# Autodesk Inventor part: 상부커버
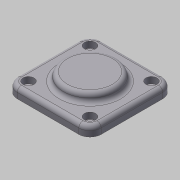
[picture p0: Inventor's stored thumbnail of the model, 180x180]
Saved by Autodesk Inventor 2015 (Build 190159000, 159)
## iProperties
Created: 2018-09
Part Number: 상부커버
Document SubType Name: Modeling
Density: 2.71 g/cm^3
Material: 알루미늄 6061
Mass: 115.614 g
Surface Area: 104.313 cm^2
Volume: 42.662 cm^3
Appearance: 알루미늄 - 평지
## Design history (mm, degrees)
sketch "스케치1"
  geometry: L1 (30, 22)-(30, -22); L2 (-22, 30)-(22, 30); L3 (-30, -22)-(-30, 22); L4 (22, -30)-(-22, -30); L5 (-30, 0)-(30, 0); L6 (0, 30)-(0, -30); C1 r 20 at (0, 0); A1 r 8 centre (22, 22) between (30, 22) and (22, 30); A2 r 8 centre (-22, 22) between (-22, 30) and (-30, 22); A3 r 8 centre (-22, -22) between (-30, -22) and (-22, -30); A4 r 8 centre (22, -22) between (22, -30) and (30, -22); 2 further points
  constraints: 12 end point, 8 point on circle, 7 midpoint, 7 tangent, 5 centre point, 3 equal radius, 2 horizontal, 1 coincident, 1 vertical
  dimensions: "d23" = 60 distance between parallel lines of L1 L3; "d25" = 60 distance between parallel lines of L4 L2; "d26" = 8 radius of A2; "d27" = 40 diameter of C1
extrude "돌출1" new body sketch "스케치1" distance "d0" = 7; taper "d1" = 0 deg
extrude "돌출2" join sketch "스케치1" distance "d2" = 10; taper "d3" = 0 deg
sketch "스케치2"
  geometry: C1 r 19 at (0, 0); 1 further point
  constraints: 1 centre point, 1 coincident
  dimensions: "d4" = 38 diameter of C1
extrude "돌출3" join sketch "스케치2" distance "d5" = 6; taper "d6" = 0 deg
fillet "모깎기1" dims "d7" = 3
fillet "모깎기2" dims "d8" = 3
sketch "스케치4"
  geometry: L1 (30, 22)-(30, -22) reference; L2 (-22, 30)-(22, 30) reference; L3 (-30, -22)-(-30, 22) reference; L4 (22, -30)-(-22, -30) reference; C1 r 22 at (0, 0) reference; A1 r 8 centre (-22, 22) between (-22, 30) and (-30, 22) reference; A2 r 8 centre (22, 22) between (30, 22) and (22, 30) reference; A3 r 8 centre (-22, 22) between (-22, 30) and (-30, 22) reference; A4 r 8 centre (-22, -22) between (-30, -22) and (-22, -30) reference; A5 r 8 centre (22, -22) between (22, -30) and (30, -22) reference; 5 further points
  constraints: 4 coincident
hole "구멍2" sketch "스케치4" at (-22, 22), (22, 22), (22, -22), (-22, -22) diameter "d28" = 4.5; stored, may be unused: countersink angle "d32" = 90 deg, drill point angle "d34" = 118 deg; dims "d29" = 6, "d30" = 8, "d31" = 4.5, "d33" = 8
fillet "모깎기3" dims "d19" = 3
chamfer "모따기1" distance "d20" = 1; stored, may be unused: second distance "d21" = 2, angle "d22" = 45 deg
node "솔리드1"
node "투영된 루프1"
